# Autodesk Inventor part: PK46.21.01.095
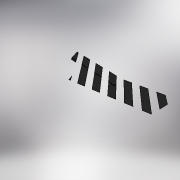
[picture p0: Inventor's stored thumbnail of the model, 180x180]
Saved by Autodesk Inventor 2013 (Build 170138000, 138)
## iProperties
Created: 2012-02
Part Number: PK46.21.01.095
Material: Aluminum-6061
Document SubType Name: Modeling
Designer: tedescj
Density: 2.71 g/cm^3
Mass: 1247.09 g
Surface Area: 3414.78 cm^2
Volume: 460.181 cm^3
Author: tedescj
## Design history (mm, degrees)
derived "PK46.21.01.094.ipt"
feature "Solid1::PK46.21.01.094.ipt"
feature "Srf7::PK46.21.01.094.ipt"
body "Srf4"
feature "Srf8::PK46.21.01.094.ipt"
body "Srf5"
feature "Srf9::PK46.21.01.094.ipt"
body "Srf6"
tag "TaggingFeature2"
body "Solid1"
body "Solid2"
